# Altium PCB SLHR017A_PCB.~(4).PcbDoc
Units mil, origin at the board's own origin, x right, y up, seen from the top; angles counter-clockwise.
Board outline 3125 x 2100 mil, 2 copper layers (Top Layer, Bottom Layer), stack 61.2 mil thick; 61 components, 25 nets, 102 pads, 30 vias.
Unrouted connection lines stored in the file: 57.
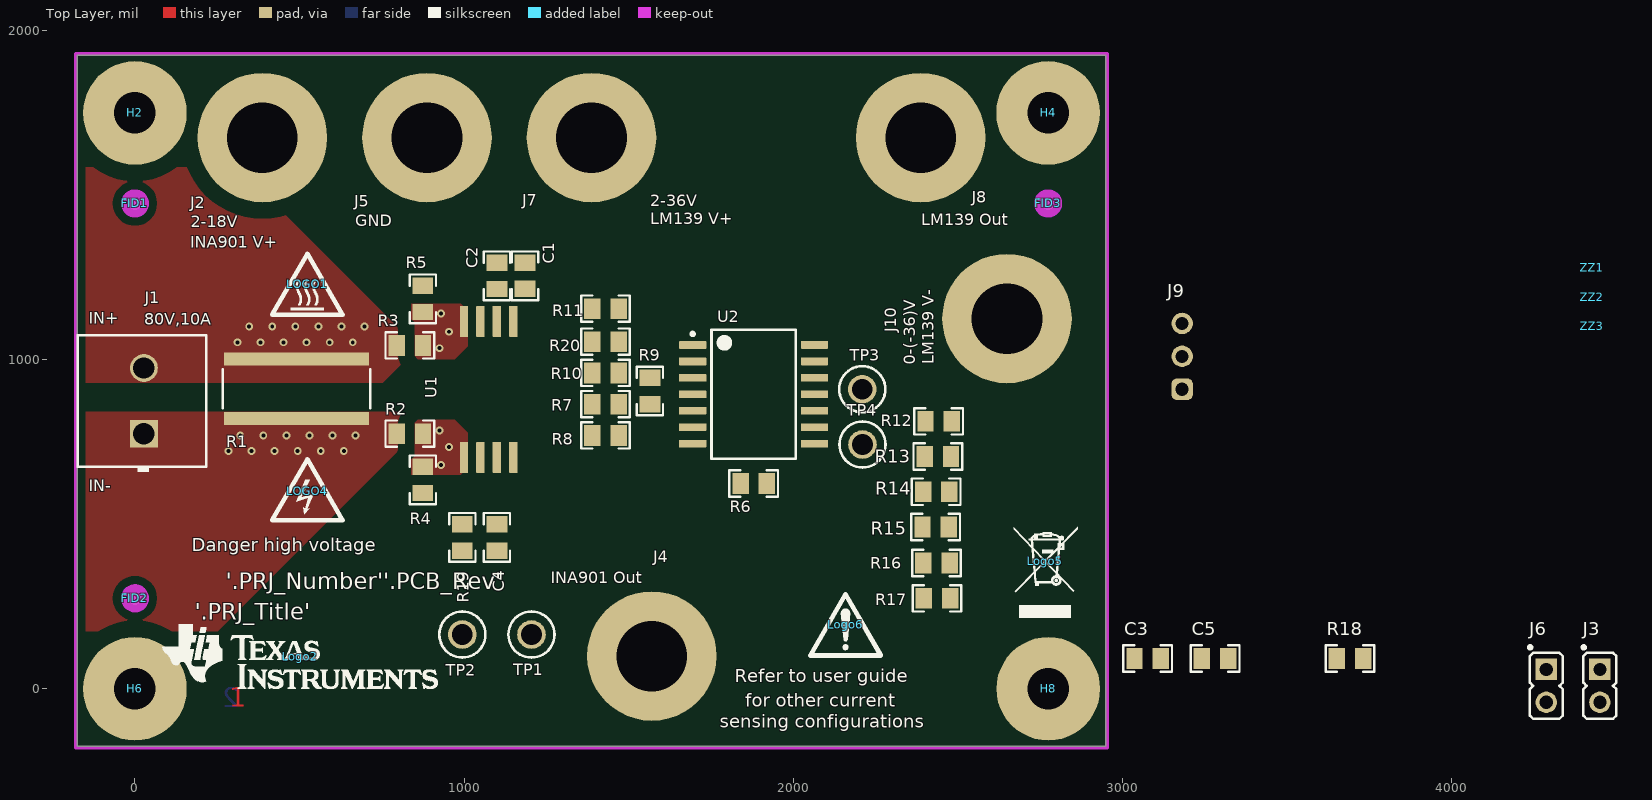
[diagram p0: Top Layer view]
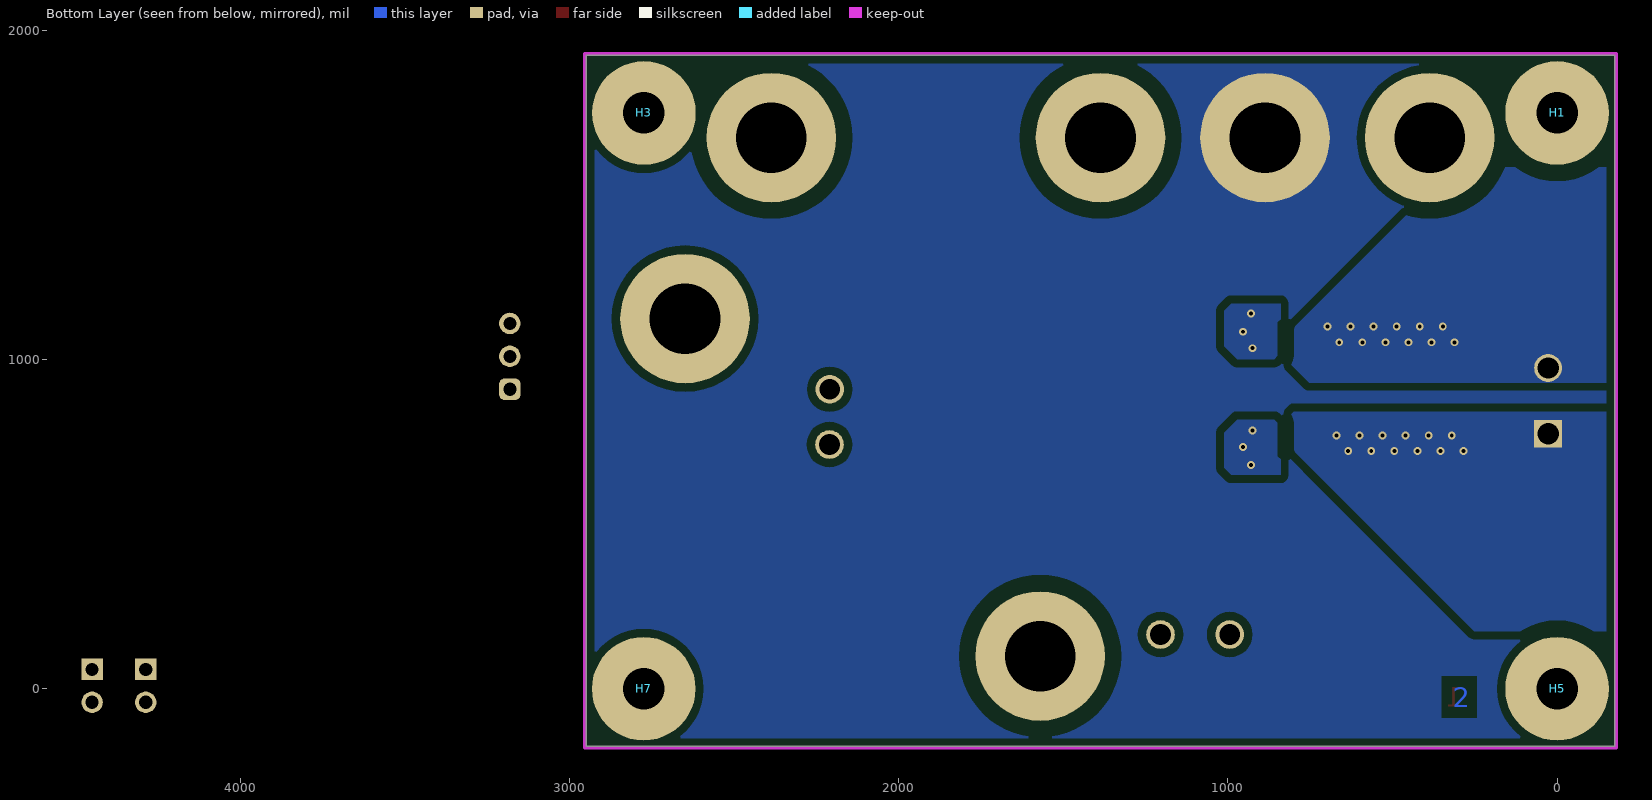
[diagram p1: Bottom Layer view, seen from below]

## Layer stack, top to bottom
Top Solder: solder mask 0.4, Solder Resist, Dk 3.5
Top Layer: signal copper 2.1
Dielectric1: core 57, FR-4 High Tg, Dk 4.8
Bottom Layer: signal copper 2.1
Bottom Solder: solder mask 0.4, Solder Resist, Dk 3.5

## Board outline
-175,-175 2950,-175 2950,1925 -175,1925
cut-out: -1791.23,-2214.56 -1781.23,-2214.56 -1781.23,-2204.56 -1791.23,-2204.56

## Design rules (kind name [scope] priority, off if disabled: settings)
AcuteAngle [All] p1: minimum=4.50000000000000E+0001 checktracksonly=FALSE
AssemblyTestPointUsage [All] p1: valid=2
Clearance Clearance_HV [InNetClass('HV_Net')] p1: gap=25 ignorepadtopadclearanceinfootprint=TRUE except(50: THPad-Poly Poly-Poly)
Clearance Clearance_Keepouts [((IsTrack Or IsArc) And Not InPoly) And IsFree and IsKeepOut vs ((IsTrack Or IsArc) And Not InPoly) And IsFree and IsKeepOut] p2: gap=0 ignorepadtopadclearanceinfootprint=FALSE
Clearance Clearance_Fiducial [InComponentClass('FiducialMark')] p3: gap=0 ignorepadtopadclearanceinfootprint=FALSE
Clearance Clearance_BoardEdge_MountingHoles [OnCopper and InComponentClass('Mounting Holes') vs IsKeepOut] p4: gap=40 ignorepadtopadclearanceinfootprint=FALSE except(15: Track-THPad)
Clearance Clearance_BoardEdge_Poly [OnCopper and InPoly vs IsKeepOut] p5: gap=25 ignorepadtopadclearanceinfootprint=FALSE
Clearance Clearance_Jack_Poly [InPolygon vs InPadClass('Jack')] p6: gap=25 ignorepadtopadclearanceinfootprint=FALSE except(50: Arc-Poly Track-Poly SMDPad-Poly THPad-Poly Via-Poly Fill-Poly Poly-Poly)
Clearance Clearance_Poly [InPolygon] p7: gap=25 ignorepadtopadclearanceinfootprint=FALSE
Clearance [All] p8: gap=15 ignorepadtopadclearanceinfootprint=FALSE
ComponentClearance ComponentClearance_MountingHoles_FiducialMarks [InComponentClass('Mounting Holes') vs InComponentClass('FiducialMark')] p1: gap=50 collisioncheckmode=3 verticalgap=10 showdistances=FALSE
ComponentClearance ComponentClearance_Logo [InComponentClass('Logo')] p2: gap=50 collisioncheckmode=3 verticalgap=100000 showdistances=FALSE
ComponentClearance ComponentClearance_ScrewToNut [(HasFootprint('NY PMS 440 0025 PH')) vs (HasFootprint('Keystone_1902C'))] p3: gap=0 collisioncheckmode=3 verticalgap=0 showdistances=FALSE
ComponentClearance ComponentClearance_MountingHoles [InComponentClass('Mounting Holes')] p4: gap=30 collisioncheckmode=3 verticalgap=100000 showdistances=FALSE
ComponentClearance [All] p5: gap=20 collisioncheckmode=3 verticalgap=10 showdistances=FALSE
DiffPairsRouting [All] p1: maxlimit=100 minlimit=10 mostfreqgap=10 toplayer_minwidth=15 toplayer_maxwidth=15 toplayer_prefwidth=15 bottomlayer_minwidth=15 bottomlayer_maxwidth=15 bottomlayer_prefwidth=15 maxuncoupledlength=1000
FabricationTestPointUsage TestPointUsage [All] p1: valid=2 allowmultiple=FALSE
FabricationTestpoint Testpoint [All] p1: side=3 testpointundercomponent=TRUE minsize=40 maxsize=100 preferedsize=60 minholesize=0 maxholesize=40 preferedholesize=32 testpointgrid=1 allowsidetop=TRUE allowsidebottom=TRUE usegrid=TRUE gridtolerance=0.01
FanoutControl Fanout_LCC [IsLCC] p1: bgadir=Out bgaviamode=Centered fanoutstyle=Auto fanoutdirection=Alternating viagrid=1 // Fanout_LCC (Default Rule)
FanoutControl Fanout_BGA [IsBGA] p2: bgadir=Out bgaviamode=Centered fanoutstyle=Auto fanoutdirection=Alternating viagrid=1 // Fanout_BGA (Default Rule)
FanoutControl Fanout_Default [All] p4: bgadir=Out bgaviamode=Centered fanoutstyle=Auto fanoutdirection=Alternating viagrid=1 // Fanout_Default (Default Rule)
FanoutControl Fanout_Small [(CompPinCount < 5)] p5: bgadir=Out bgaviamode=Centered fanoutstyle=Auto fanoutdirection=OutThenIn viagrid=1 // Fanout_Small (Default Rule)
HoleSize [All] p1: absolutevalues=TRUE maxlimit=251 minlimit=8 maxpercent=80.000 minpercent=20.000
MinimumAnnularRing [All] p1: minimumring=6
MinimumSolderMaskSliver MinimumSolderMaskSliver_Logo [InComponentClass('Logo') vs InComponentClass('Logo')] p1: minsoldermaskwidth=0.7
MinimumSolderMaskSliver [All] p2: minsoldermaskwidth=4
PlaneConnect [All] p1: planeconnectstyle=Relief reliefexpansion=10 reliefentries=4 reliefconductorwidth=10 reliefairgap=10
PolygonConnect [All] p1: connectstyle=Direct reliefconductorwidth=30 reliefentries=4 polygonreliefangle="90 Angle" airgapwidth=15
RoutingVias [All] p1: holewidth=12 width=24 viastyle="Through Hole" minholewidth=12 minwidth=24 maxholewidth=12 maxwidth=24
SilkToBoardRegionClearance [Not ((IsComment or IsDesignator) And (Hide <> 'False')) and not InRegion(1000,500,4000,800)] p1:
SilkToSilkClearance SilkToSilkClearance_Pb-FreeLogo [(HasFootprint('Pb-Free_Overlay_Medium') OR HasFootprint('Pb-Free_Overlay_Small')) vs (HasFootprint('Pb-Free_Overlay_Medium') OR HasFootprint('Pb-Free_Overlay_Small'))] p1: silktosilkclearance=0
SilkToSilkClearance [All] p2: silktosilkclearance=4
SilkToSolderMaskClearance SilkToComonentPadClearance [IsPad and InAnycomponent] p1: minsilkscreentomaskgap=5 clearancetoexposedcopper=TRUE
SilkToSolderMaskClearance "Silk to Solder Mask Opening" [All] p2: minsilkscreentomaskgap=4 clearancetoexposedcopper=FALSE
SolderMaskExpansion [All] p1: expansion=0
Width [All] p1: maxlimit=100 minlimit=6 preferedwidth=10 checkconnectedcopper=TRUE
15 further rules are at their usual default settings.

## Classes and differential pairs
component class Header: J3 J6 J9
component class SLHR017A_MainSheet: C1 C2 C3 C4 C5 J1 J2 J3 J4 J5 J6 J7 J8 J9 J10 R1 R2 R3 R4 R5 R6 R7 R8 R9 R10 R11 R12 R13 R14 R15 R16 R17 R18 R19 R20 TP1 TP2 TP3 TP4 U1 U2 U4
component class AssemblyNote: ZZ1 ZZ2 ZZ3
component class FiducialMark: FID1 FID2 FID3
component class SLHR017A_Hardware: FID1 FID2 FID3 H1 H2 H3 H4 H5 H6 H7 H8 LOGO1 Logo2 Logo3 LOGO4 Logo5 Logo6 Logo7 ZZ1 ZZ2 ZZ3
component class Logo: Logo2
component class "Mounting Holes": H2 H4 H6 H8
pad class Jack: J3-1 J4-1 J6-1 J7-1 J8-1

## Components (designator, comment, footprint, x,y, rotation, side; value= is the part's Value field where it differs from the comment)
C1 "C0805C104K1RACTU" 0805_HV 1185.18,1255.18 r90 top value=0.1uF
C2 "C0805C103F1GACTU" 0805_HV 1100,1255 r90 top value=0.01uF
C3 "C0805C101J1RACTU" 0805_HV 3077.5,92 r0 top value=100pF
C4 "C0805C103F1GACTU" 0805_HV 1100,460 r270 top value=0.01uF
C5 "C0805C103F1GACTU" 0805_HV 3282.5,92 r0 top value=0.01uF
FID1 "Fiducial" Fiducial10-20 0,1475 r270 top locked
FID2 "Fiducial" Fiducial10-20 0,275 r0 top locked
FID3 "Fiducial" Fiducial10-20 2775,1475 r180 top locked
H1 "1902C" Keystone_1902C 0,1750 r180 bottom locked
H2 "NY PMS 440 0025 PH" "NY PMS 440 0025 PH" 0,1750 r0 top locked
H3 "1902C" Keystone_1902C 2775,1750 r180 bottom locked
H4 "NY PMS 440 0025 PH" "NY PMS 440 0025 PH" 2775,1750 r0 top locked
H5 "1902C" Keystone_1902C 0,0 r180 bottom locked
H6 "NY PMS 440 0025 PH" "NY PMS 440 0025 PH" 0,0 r0 top locked
H7 "1902C" Keystone_1902C 2775.53,0 r180 bottom locked
H8 "NY PMS 440 0025 PH" "NY PMS 440 0025 PH" 2775.53,0 r0 top locked
J1 "039544-3002" Molex_039544-3002 27.17,875 r90 top
J2 "V+" Keystone_575-4 387.5,1675 r0 top
J3 "PBC02SAAN" Sullins_PBC02SAAN 4451.62,9 r0 top
J4 "INA_OUT" Keystone_575-4 1570.77,99.44 r0 top
J5 "GND" Keystone_575-4 887.5,1675 r0 top
J6 "PBC02SAAN" Sullins_PBC02SAAN 4288.84,9 r0 top
J7 "VPULLUP" Keystone_575-4 1387.5,1675 r0 top
J8 "COMP_OUT" Keystone_575-4 2387.5,1675 r0 top
J9 "TSW-103-07-G-S" TSW-103-07-G-S 3182.31,1010.33 r90 top
J10 "V-" Keystone_575-4 2650,1125 r0 top
LOGO1 "CAUTION HOT SURFACE" IEC_HotSurface_Small 524,1229.94 r0 top
Logo2 "Texas Instruments" TI_Stacked_Overlay_Small 502.13,97.86 r0 top
Logo3 "FCC disclaimer" FCC_disclaimer 1947.51,-1477.18 r270 top locked
LOGO4 "DANGER HIGH VOLTAGE" IEC_HighVoltage_Small 524,599.72 r0 top
Logo5 "WEEE logo" WEEE_Minimum 2765.79,387.53 r0 top
Logo6 "CAUTION.  READ USER GUIDE BEFORE USE" IEC_Caution_Small 2159.38,194.38 r0 top
R1 "KRL11050-C-R050-F-T1" 4320 490.99,911.59 r90 top locked value=0.05
R2 "ERJ-6GEY0R00V" 0805_HV 835.36,775.33 r0 top value=0
R3 "ERJ-6GEY0R00V" 0805_HV 835.36,1043.51 r0 top value=0
R4 "ERJ-6GEY0R00V" 0805_HV 875,635 r90 top value=0
R5 "ERJ-6GEY0R00V" 0805_HV 875,1185 r270 top value=0
R6 "ERJ-6GEY0R00V" 0805_HV 1880.36,623.81 r180 top value=0
R7 "ERJ-6GEY0R00V" 0805_HV 1430,865 r0 top value=0
R8 "ERJ-6GEY0R00V" 0805_HV 1430,770 r0 top locked value=0
R9 "ERJ-6GEYJ153V" 0805_HV 1565,905 r90 top locked value=15k
R10 "ERJ-6GEYJ153V" 0805_HV 1430,960 r0 top value=15k
R11 "ERJ-6GEYJ302V" 0805_HV 1430,1155 r180 top value=3.0k
R12 "RNCP0805FTD10K0" 0805_HV 2442.37,812.84 r180 top value=10.0k
R13 "CRCW080510M0FKEA" 0805_HV 2439.87,705.83 r0 top value=10.0Meg
R14 "RNCP0805FTD10K0" 0805_HV 2434.95,598.82 r0 top value=10.0k
R15 "CRCW080510M0FKEA" 0805_HV 2433.32,491.52 r0 top value=10.0Meg
R16 "RNCP0805FTD10K0" 0805_HV 2435.86,382.18 r0 top value=10.0k
R17 "CRCW080510M0FKEA" 0805_HV 2437.24,274.88 r0 top value=10.0Meg
R18 "RNCP0805FTD10K0" 0805_HV 3692.5,92 r0 top value=10.0k
R19 "RNCP0805FTD10K0" 0805_HV 994.96,460 r90 top value=10.0k
R20 "RNCP0805FTD10K0" 0805_HV 1430,1055 r180 top value=10.0k
TP1 "5010" Keystone5010 1204.96,164.96 r90 top
TP2 "5010" Keystone5010 994.96,164.96 r90 top
TP3 "5010" Keystone5010 2210.23,910.38 r90 top
TP4 "5010" Keystone5010 2210.94,742.37 r90 top
U1 "INA901HKX/EM" HKX0008A_Custom_B 1075,910 r90 top
U2 "LM139AWGRLQMLV" NAC0014A_N 1880,895 r0 top
ZZ1 "These assemblies are ESD sensitive, ESD precautions shall be observed." AssemblyNote 4427.97,1278.79 r0 top
ZZ2 "These assemblies must be clean and free from flux and all contaminants. Use of no clean flux is not acceptable." AssemblyNote 4427.97,1190.24 r0 top
ZZ3 "These assemblies must comply with workmanship standards IPC-A-610 Class 2, unless otherwise specified." AssemblyNote 4427.97,1101.68 r0 top

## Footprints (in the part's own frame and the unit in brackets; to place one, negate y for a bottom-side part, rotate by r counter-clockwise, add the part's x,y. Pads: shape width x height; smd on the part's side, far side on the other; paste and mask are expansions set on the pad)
0805_HV [mil] "0805 with 30mil clearance between pads"
  rect 50x63 smd: 1(-40,0) 2(40,0)
  silkscreen extent -74,-40 74,40, body extent -43,-29 43,29, height 57
4320 [mm] "SUSUMU"
  rect 1x11.2 smd: 1(-2.3,0) 2(2.3,0)
  silkscreen extent -1.5,-5.7 1.5,5.7, body extent -2.6,-5.6 2.6,5.6, height 0.7
AssemblyNote [mil] "Assembly Note"
FCC_disclaimer [mil]
Fiducial10-20 [mm]
  round 1 smd mask+0.5: 1(0,0)
  Top Layer keep-out circle w1.178: c0,0 r0.5
HKX0008A_Custom_B [mm] "CFP, 8-Leads, Body 6.73x6.74mm (max), Pitch 1.27mm, IPC Medium Density"
  rrect15% 2.4x0.65 smd: 1(-5.25,1.905) 2(-5.25,0.635) 3(-5.25,-0.635) 4(-5.25,-1.905) 5(5.25,-1.905) 6(5.25,-0.635) 7(5.25,0.635) 8(5.25,1.905)
  body extent -3.25,-3.24 3.25,3.24, height 2.51
IEC_Caution_Small [mil]
  silkscreen extent -107,-93 107,92
IEC_HighVoltage_Small [mil]
  silkscreen extent -107,-88 107,97
IEC_HotSurface_Small [mil]
  silkscreen extent -107,-93 107,92
Keystone5010 [mil] "Keystone Multipurpose loops"
  round 87 hole 63: 1(0,0)
  silkscreen extent -70,-70 70,70, body extent -63,-63 63,62, height 319
Keystone_575-4 [mm] "Banana Jack"
  round 10 hole 5.45: 1(0,0)
  body extent -3.95,-3.95 3.92,3.93, height 2.36
Keystone_1902C [mil] "Hex Standoff, 4-40 threaded, nylon"
  round 1 on Mech4: 0(0,0)
  body extent -145,-126 146,126, height 501
Molex_039544-3002 [mm] "Terminal Block, 5.08mm, 2x1, TH"
  rect 2.15x2.15 hole 1.65: 1(-2.54,0)
  round 2.15 hole 1.65: 2(2.54,0)
  silkscreen extent -5.5,-4.8 5.08,5.11, body extent -5.08,-4.8 5.08,5.11, height 14.48
NAC0014A_N [mm] "CFP-14"
  rrect17% 2.1x0.6 smd: 1(-4.7,3.81) 2(-4.7,2.54) 3(-4.7,1.27) 4(-4.7,0) 5(-4.7,-1.27) 6(-4.7,-2.54) 7(-4.7,-3.81) 8(4.7,-3.81) 9(4.7,-2.54) 10(4.7,-1.27) 11(4.7,0) 12(4.7,1.27) 13(4.7,2.54) 14(4.7,3.81)
  silkscreen extent -4.82,-4.97 3.25,4.97, body extent -5.21,-4.95 5.21,4.95, height 1.99
"NY PMS 440 0025 PH" [mm] "4-40 nylon screw and mounting hole"
  round 8 hole 3.2: 1(0,0)
  body extent -3.3,-3.3 3.3,3.3, height 2.69
Sullins_PBC02SAAN [mm] "Sullins 100mil, 1x2, 230 mil above insulator"
  rect 1.65x1.65 hole 1.016: 1(0,1.27)
  round 1.65 hole 1.016: 2(0,-1.27)
  silkscreen extent -1.37,-2.54 1.27,3.1, body extent -1.27,-2.54 1.27,2.54, height 8.38
TI_Stacked_Overlay_Small [mil]
  silkscreen extent -418,-98 418,98
TSW-103-07-G-S [mm] "Samtec 100mil, 1x3, 230 mil above insulator"
  rrect50% 1.65x1.65 hole 1.016: 1(-2.54,0)
  round 1.65 hole 1.016: 2(0,0) 3(2.54,0)
  body extent -3.81,-1.27 3.81,1.27, height 8.38
WEEE_Minimum [mil] "WEEElie bin"
  silkscreen extent -95,-172 99,104

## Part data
C1: library part CMP-0007722-2, "CAP, CERM, 0.1 uF, 100 V, +/- 10%, X7R, 0805", Cap_Case=0805, Manufacturer=Kemet, Supplier Part Number 1=399-3486-1-ND, TempCo=X7R, Tolerance_%=10%, Value1="0.064 ohm", Value2=100V, ValueDisplayed=0.1uF
C2 C4 C5: library part CMP-0007716-2, "CAP, CERM, 0.01 uF, 100 V, +/- 1%, C0G/NP0, 0805", Cap_Case=0805, Manufacturer=Kemet, Supplier Part Number 1=399-11160-1-ND, TempCo=C0G/NP0, Tolerance_%=1%, Value1=Unknown, Value2=100V, ValueDisplayed=0.01uF
C3: library part CMP-0007706-2, "CAP, CERM, 100 pF, 100 V, +/- 5%, X7R, 0805", Cap_Case=0805, Manufacturer=Kemet, Supplier Part Number 1=80-C0805C101J1R, TempCo=X7R, Tolerance_%=5%, Value1=Unknown, Value2=100V, ValueDisplayed=100pF
FID1 FID2 FID3: library part CMP-0077181-1, "Fiducial mark.  There is nothing to buy or mount.", Manufacturer=N/A
H1 H3 H5 H7: library part CMP-0003610-1, "Standoff, Hex, 0.5\"L #4-40 Nylon", Manufacturer=Keystone, Supplier Part Number 1=36-1902C-ND
H2 H4 H6 H8: library part CMP-0003617-1, "Machine Screw, Round, #4-40 x 1/4, Nylon, Philips panhead", Manufacturer="B&F Fastener Supply", Supplier Part Number 1=H542-ND
J1: library part CMP-0055345-1, "Terminal Block, 5.08mm, 2x1, TH", Color=Black, Current_A=15A, Manufacturer=Molex, Supplier Part Number 1=WM7853-ND, Voltage_V=300V
J2 J4 J5 J7 J8 J10: library part CMP-0055165-2, "Standard Banana Jack, Uninsulated, 5.5mm", Manufacturer=Keystone, PartNumber=575-4, Supplier Part Number 1=36-575-4-ND
J3 J6: library part CMP-0054566-1, "Header, 100mil, 2x1, Gold, TH", Color=Black, Current_A=3A, Manufacturer="Sullins Connector Solutions", Supplier Part Number 1=S1011E-02-ND, Voltage_V=1.8kV
J9: library part CMP-0075407-2, "Header, 100mil, 3x1, Gold, TH", Color=Black, Current_A=6.3A, Manufacturer=Samtec, Supplier Part Number 1=SAM1029-03-ND, Voltage_V=550V
LOGO1: library part CMP-0074837-1, "IEC 61010-1 Hot Surface Warning"
Logo2: library part CMP-0074838-1, "Texas Instrument Corporate Signature"
Logo3: library part CMP-0074847-1, "FCC_disclaimer"
LOGO4: library part CMP-0074835-1, "IEC 61010-1 High Voltage Warning"
Logo5: library part CMP-0074769-1
Logo6: library part CMP-0074836-1, "IEC 61010-1 Caution Warning"
R1: library part CMP-0015099-2, "RES, 0.05, 1%, 6 W, 4320_WIDE", Manufacturer="Susumu Co Ltd", Power_W=6W, Supplier Part Number 1=KRL11C.050CT-ND, TempCo="50 ppm/C", Tolerance_%=1%, Value_Code=R050, ValueDisplayed=0.05
R2 R3 R4 R5 R6 R7 R8: library part CMP-0020616-3, "RES, 0, 5%, 0.125 W, AEC-Q200 Grade 0, 0805", Manufacturer=Panasonic, Power_W=125mW, Supplier Part Number 1=P0.0ACT-ND, TempCo="600 ppm/C", Tolerance_%=5%, Value2=0.125W, Value_Code=0000, ValueDisplayed=0
R9 R10: library part CMP-0020646-3, "RES, 15 k, 5%, 0.125 W, AEC-Q200 Grade 0, 0805", Manufacturer=Panasonic, Power_W=125mW, Supplier Part Number 1=P15KACT-ND, TempCo="200 ppm/C", Tolerance_%=5%, Value2=0.125W, Value_Code=15k0, ValueDisplayed=15k
R11: library part CMP-0020698-3, "RES, 3.0 k, 5%, 0.125 W, AEC-Q200 Grade 0, 0805", Manufacturer=Panasonic, Power_W=125mW, Supplier Part Number 1=P3.0KACT-ND, TempCo="200 ppm/C", Tolerance_%=5%, Value2=0.125W, Value_Code=3k00, ValueDisplayed=3.0k
R12 R14 R16 R18 R19 R20: library part CMP-0084247-1, "RES, 10.0 k, 1%, 0.25 W, AEC-Q200 Grade 0, 0805", Manufacturer="Stackpole Electronics Inc", Power_W=250mW, TempCo="100 ppm/C", Tolerance_%=1%, Value2=0.25W, Value_Code=10k0, ValueDisplayed=10.0k
R13 R15 R17: library part CMP-0020846-3, "RES, 10.0 M, 1%, 0.125 W, AEC-Q200 Grade 0, 0805", Manufacturer=Vishay-Dale, Power_W=125mW, Supplier Part Number 1=541-10.0MCCT-ND, TempCo="100 ppm/C", Tolerance_%=1%, Value2=0.125W, Value_Code=10M0, ValueDisplayed=10.0M
TP1 TP2 TP3 TP4: library part CMP-0055147-1, "Test Point, Multipurpose, Red, TH", Color=Red, Manufacturer=Keystone, Supplier Part Number 1=36-5010-ND
U1: library part CMP-0081563-2, "Voltage Output, Unidirectional Measurement Current-Shunt Monitor, HKX0008A (CFP-8)", Alternate Manufacturer="Texas Instruments", Rating=Space
U2: library part CMP-0068426-2, "Low Power Low Offset Voltage Quad Comparator, NAC0014A (CFP-14)", Manufacturer="Texas Instruments", Operating Temperature Range="-55 to 125 C", Rating=Space
ZZ1: library part CMP-0077236-1
ZZ2: library part CMP-0077237-1
ZZ3: library part CMP-0077238-1

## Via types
v1: diameter 24, hole 12, Top Layer to Bottom Layer, tented both sides, 30 vias

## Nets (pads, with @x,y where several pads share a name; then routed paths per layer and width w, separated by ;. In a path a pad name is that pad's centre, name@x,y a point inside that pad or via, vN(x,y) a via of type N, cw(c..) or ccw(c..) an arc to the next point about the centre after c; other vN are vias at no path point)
GND: C1.2 C2.2 C4.2 J5.1 J9.1 R4.1 R5.1 R10.1 R12.1 R13.1 R14.1 R15.1 R16.1 R17.1 R18.2 R19.2 R20.2 U1.2
NetC1_1: C1.1 C2.1 J2.1 J3.1 U1.6 U2.3
NetC3_1: C3.1 R3.2 R5.2 U1.8
  other v1: 925,1035 955,1085 930,1140
NetC3_2: C3.2 R2.2 R4.2 U1.1
  other v1: 930,680 955,735 925,785
NetC4_1: C4.1 R6.1 TP1.1 U1.4
NetC5_1: C5.1 R6.2 TP2.1 U1.3
NetC5_2: C5.2 J4.1 R7.1 R8.1 U1.5
NetJ1_1: J1.1 R1.1 R2.1
  other v1: 284.71,722.65 354.71,722.65 424.71,722.65 494.71,722.65 564.71,722.65 634.71,722.65 320.06,770.19 390.06,770.19 460.06,770.19 530.06,770.19 600.06,770.19 670.06,770.19
NetJ1_2: J1.2 R1.2 R3.1
  other v1: 311.93,1052.99 381.93,1052.99 451.93,1052.99 521.93,1052.99 591.93,1052.99 661.93,1052.99 347.28,1100.53 417.28,1100.53 487.28,1100.53 557.28,1100.53 627.28,1100.53 697.28,1100.53
NetJ3_2: J3.2 J6.1 R9.2
NetJ6_2: J6.2 J7.1 R11.2
NetJ8_1: J8.1 R11.1 U2.2
NetJ9_2: J9.2 U2.12
NetJ9_3: J9.3 J10.1
NetR7_2: R7.2 R9.1 R10.2 TP3.1 U2.4
NetR8_2: R8.2 TP4.1 U2.5
NetR12_2: R12.2 U2.8
NetR13_2: R13.2 U2.9
NetR14_2: R14.2 U2.6
NetR15_2: R15.2 U2.7
NetR16_2: R16.2 U2.10
NetR17_2: R17.2 U2.11
NetR18_1: R18.1 U2.1
NetR19_1: R19.1 U2.13
NetR20_1: R20.1 U2.14
pads on no net: FID1.1 FID2.1 FID3.1 H1.0 H2.1 H3.0 H4.1 H5.0 H6.1 H7.0 H8.1 U1.7

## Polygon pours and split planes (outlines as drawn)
NetC3_2 on Top Layer "GND" (solid, remove dead copper, pour order 264): 840.29,649.85 840.29,696.87 849.75,706.32 849.75,808.11 859.85,818.22 972.21,818.22 1011.88,778.55 1011.88,671.56 990.17,649.85
NetC3_1 on Top Layer "GND" (solid, remove dead copper, pour order 265): 840.29,1170.15 840.29,1122.86 849.75,1113.4 849.75,1011.89 859.85,1001.78 972.21,1001.78 1011.88,1041.45 1011.88,1148.44 990.17,1170.15
NetJ1_1 on Top Layer "GND" (solid, remove dead copper, pour order 266): -174.94,842.31 799.54,842.31 820.22,821.63 820.22,743.75 717.82,641.35 251.68,175.21 -172.82,175.21
NetJ1_2 on Top Layer "GND" (solid, remove dead copper, pour order 267): -175.09,930.77 752.62,930.77 820.22,998.37 820.22,1076.25 717.82,1178.65 310.93,1585.54 -173.01,1585.54
GND on Bottom Layer "GND" (solid, remove dead copper, pour order 272): -174.92,-174.96 2949.91,-174.96 2949.92,-174.96 2949.92,1925.05 2949.89,1925.07 -174.89,1925.07 -175,1924.96
NetC3_1 on Bottom Layer "GND" (solid, remove dead copper, pour order 269): 840.29,1170.15 840.29,1122.86 849.75,1113.4 849.75,1011.89 859.85,1001.78 972.21,1001.78 1011.88,1041.45 1011.88,1148.44 990.17,1170.15
NetC3_2 on Bottom Layer "GND" (solid, remove dead copper, pour order 268): 840.29,649.85 840.29,696.87 849.75,706.32 849.75,808.11 859.85,818.22 972.21,818.22 1011.88,778.55 1011.88,671.56 990.17,649.85
NetJ1_1 on Bottom Layer "GND" (solid, remove dead copper, pour order 270): -174.94,842.31 799.54,842.31 820.22,821.63 820.22,743.75 717.82,641.35 251.68,175.21 -172.82,175.21
NetJ1_2 on Bottom Layer "GND" (solid, remove dead copper, pour order 271): -175.09,930.77 752.62,930.77 820.22,998.37 820.22,1076.25 717.82,1178.65 310.93,1585.54 -173.01,1585.54

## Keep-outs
Keep-Out Layer:
  lines w10: -180,-180 2955,-180 2955,1930 -180,1930 -180,-180
  text ".Layer_Name" at -522.23,-1539.06 h60

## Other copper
Top Layer:
  text "1" at 287.08,-55.09 h60
  text ".Layer_Name" at -522.23,-1539.06 h60
Bottom Layer:
  text "2" at 316.97,-55.48 h60
  text ".Layer_Name" at -522.23,-1539.06 h60

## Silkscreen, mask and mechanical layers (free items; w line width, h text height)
Top Overlay:
  text "2-36V" at 1566.56,1466.79 h35
  text "LM139 V+" at 1566.01,1412.12 h35
  text "LM139 Out" at 2390.02,1409.42 h35
  text "GND" at 669.35,1405.39 h35
  text "2-18V" at 169.23,1402.02 h35
  text "INA901 V+" at 168.19,1339.58 h35
  text "IN+" at -139.72,1109.97 h35
  text "80V,10A" at 28.26,1106.78 h35
  text "LM139 V-" at 2427.31,986.4 h35 r90
  text "0-(-36)V" at 2371.89,984.24 h35 r90
  text "IN-" at -139.72,599.99 h35
  text "Danger high voltage" at 172.24,418.2 h40
  text "INA901 Out" at 1263.83,321.35 h35
  text "'.PRJ_Number''.PCB_Rev'" at 276.6,302.79 h50
  text "'.PRJ_Title'" at 182.3,210.53 h50
  text "Refer to user guide" at 1822.52,19.52 h40
  text "for other current" at 1854.54,-54.96 h40
  text "sensing configurations" at 1776.8,-118.4 h40
  text ".Layer_Name" at -522.23,-1539.06 h60
Bottom Overlay:
  text ".Layer_Name" at -522.23,-1539.06 h60
Top Paste:
  text ".Layer_Name" at -522.23,-1539.06 h60
Bottom Paste:
  text ".Layer_Name" at -522.23,-1539.06 h60
Top Solder:
  text ".Layer_Name" at -522.23,-1539.06 h60
  text ".Layer_Name" at -522.23,-1539.06 h60
Bottom Solder:
  text ".Layer_Name" at -522.23,-1539.06 h60
Drill Guide:
  text ".Layer_Name" at -522.23,-1539.06 h60
M1 Board Outline:
  the board outline again, w10
  text ".Layer_Name" at -522.23,-1539.06 h60
M2 Board Dimensions:
  rectangle: -974.23,-1080.56 -599.23,-955.56
  rectangle: -1099.23,-955.56 -974.23,-830.56
  lines w7: -1099.23,-955.56 -99.23,-955.56 ; -974.23,-1080.56 -974.23,-830.56 ; -849.23,-1080.56 -849.23,-830.56 ; -599.23,-1080.56 -599.23,-830.56 ; -349.23,-1080.56 -349.23,-830.56 ; -1099.23,-1080.56 -1099.23,-830.56 -99.23,-830.56 -99.23,-1080.56 -1099.23,-1080.56
  text ".Layer_Name" at -522.23,-1539.06 h60
M3 3D STEP Top:
  text ".Layer_Name" at -522.23,-1539.06 h60
M4 3D STEP Bottom:
  text ".Layer_Name" at -522.23,-1539.06 h60
M5 Assembly Top:
  lines w10: -1391.23,-1610.73 5208.77,-1610.73 ; -1391.23,-1407.4 5210.77,-1407.4 ; -1391.23,-1204.06 -1391.23,-1814.06 2613.77,-1814.06 5210.77,-1814.06 5210.77,-1204.06 -1390.73,-1204.06 -1390.73,-1814.06 184.77,-1814.06 ; 1073.77,-1814.06 1073.77,-1204.06 ; 2340.77,-1407.4 2340.77,-1204.06 ; 3180.77,-1407.4 3180.77,-1204.06 ; 3802.77,-1820.56 3802.77,-1617.73
  text "COMPONENTS MARKED 'DNP' SHOULD NOT BE POPULATED." at 54.27,-999.06 h60
  text "ASSEMBLY VARIANT:" at 53.77,-1114.56 h60
  text ".VariantName" at 1089.77,-1114.56 h60
  text "PCB VIEWED FROM TOP SIDE" at -1327.73,-1336.23 h60
  text "BOARD #:" at 1148.77,-1336.23 h60
  text ".PRJ_Number" at 1694.27,-1336.23 h60
  text "REV:" at 2538.77,-1336.23 h60
  text ".PCB_Rev" at 2830.27,-1336.23 h60
  text "SVN REV:" at 3376.77,-1336.23 h60
  text ".VersionControl_RevNumber" at 3882.77,-1336.23 h60
  text "TID #:" at 1148.77,-1539.56 h60
  text ".TID" at 1694.27,-1539.56 h60
  text "PLOT NAME =" at -1327.73,-1744.9 h60
  text ".plot_File_Name" at -522.23,-1744.9 h60
  text "GENERATED    :" at 1150.77,-1744.9 h60
  text ".Print_Date" at 2020.27,-1744.9 h60
  text ".Print_Time" at 2749.27,-1744.9 h60
  text "TEXAS INSTRUMENTS" at 4013.77,-1744.9 h60
M6 Assembly Bottom:
  lines w10: -1391.73,-1407.9 5210.27,-1407.9 ; -1389.73,-1611.23 5210.27,-1611.23 ; 16.27,-1821.06 16.27,-1618.23 ; 638.27,-1407.9 638.27,-1204.56 ; 1478.27,-1407.9 1478.27,-1204.56 ; 2745.27,-1814.56 2745.27,-1204.56 ; 3634.27,-1814.56 5209.77,-1814.56 5209.77,-1204.56 -1391.73,-1204.56 -1391.73,-1814.56 1205.27,-1814.56 5210.27,-1814.56 5210.27,-1204.56
  text "COMPONENTS MARKED 'DNP' SHOULD NOT BE POPULATED." at 5002.77,-998.56 h60
  text ".VariantName" at 3958.77,-1114.56 h60
  text "ASSEMBLY VARIANT:" at 4997.77,-1114.56 h60
  text ".VersionControl_RevNumber" at -63.73,-1336.73 h60
  text "SVN REV:" at 442.27,-1336.73 h60
  text ".PCB_Rev" at 988.77,-1336.73 h60
  text "REV:" at 1280.27,-1336.73 h60
  text ".PRJ_Number" at 2124.77,-1336.73 h60
  text "BOARD #:" at 2670.27,-1336.73 h60
  text "PCB VIEWED FROM BOTTOM SIDE" at 5146.77,-1336.73 h60
  text ".TID" at 2124.77,-1540.06 h60
  text "TID #:" at 2670.27,-1540.06 h60
  text "TEXAS INSTRUMENTS" at -194.73,-1745.4 h60
  text ".Print_Time" at 1069.77,-1745.4 h60
  text ".Print_Date" at 1798.77,-1745.4 h60
  text "GENERATED    :" at 2668.27,-1745.4 h60
  text ".plot_File_Name" at 4341.27,-1745.4 h60
  text "PLOT NAME =" at 5146.77,-1745.4 h60
M7 LPKF Text Top:
  text ".Layer_Name" at -522.23,-1539.06 h60
M8 LPKF Text Bottom:
  text ".Layer_Name" at -522.23,-1539.06 h60
M9 Title Sheet:
  drawing of 57 lines, arcs and shapes, not listed
  text "1" at -359.39,7355.94 h70
  text "2" at 2136.27,7355.94 h70
  text "3" at 4625.61,7355.94 h70
  text "4" at 7132.28,7355.94 h70
  text "5" at 9631.27,7355.94 h70
  text "6" at 12136.27,7355.94 h70
  text "A" at -1515.73,6212.94 h70
  text "A" at 13284.27,6212.94 h70
  text "B" at -1515.73,3832.94 h70
  text "B" at 13284.27,3832.94 h70
  text "C" at -1515.73,1457.94 h70
  text "C" at 13284.27,1457.94 h70
  text "PROJECT TITLE:" at 10244.27,-403.06 h45
  text ".PRJ_Title" at 10294.27,-536.39 h70
  text "DESIGNED FOR:" at 10244.27,-704.06 h45
  text ".PRJ_Customer" at 10294.27,-844.06 h70
  text "D" at -1515.73,-912.06 h70
  text "D" at 13284.27,-912.06 h70
  text "FILE NAME:" at 10244.27,-1004.06 h45
  text ".PCB_File_Name_No_Path" at 10294.27,-1124.06 h70
  text "Texas Instruments (TI) and/or its licensors do not warrant the accuracy or completeness of this specification" at 5274.77,-1285.9 h45
  text "ENGINEER:" at 10244.27,-1294.06 h45
  text "LAYOUT BY:" at 11749.27,-1294.06 h45
  text "or any information contained therein. TI and/or its licensors do not warrant that this design will meet" at 5229.79,-1398.57 h45
  text ".PRJ_Engineer" at 10294.27,-1449.05 h70
  text ".PCB_Layout" at 11799.77,-1449.05 h70
  text "the specifications, will be suitable for your application or fit for any particular purpose, or will operate in" at 5229.79,-1511.23 h45
  text ".Layer_Name" at -522.23,-1539.06 h60
  text "ALTIUM DESIGNER VERSION:" at 11749.27,-1604.06 h45
  text "an implementation. TI and/or its licensors do not warrant that the design is production worthy. You should" at 5229.79,-1623.9 h45
  text "completely validate and test your design implementation to confirm the system functionality for your application." at 5274.77,-1736.56 h45
  text ".print_Scale" at 10294.27,-1737.39 h70
  text ".Application_BuildNumber" at 11799.77,-1737.39 h70
  text "1" at -359.39,-1944.06 h70
  text "2" at 2136.27,-1944.06 h70
  text "3" at 4625.61,-1944.06 h70
  text "4" at 7132.28,-1944.06 h70
  text "5" at 9631.27,-1944.06 h70
  text "6" at 11488.98,-1949.87 h70
  text "WO#307451-7449-D" at 11888.89,-1952.37 h70
M10 Fab Notes:
  drawing of 189 lines, arcs and shapes, not listed
  text "DESIGN INFORMATION" at 11296.29,5675.61 h60
  text "20" at 11706.72,5544.28 h60
  text "MIN. TRACK WIDTH:" at 10651.73,5543.49 h60
  text "MIL" at 11902.73,5543.49 h60
  text "MIN. CLEARANCE:" at 10651.73,5419.36 h60
  text "MIL" at 11902.73,5419.36 h60
  text "19.7" at 11661.15,5416.95 h60
  text "24" at 11687.7,5303.69 h60
  text "MIN. VIA PAD SIZE:" at 10651.73,5295.23 h60
  text "MIL" at 11902.73,5295.23 h60
  text "0.05mm (2MIL)" at 11346.73,5165.33 h60
  text "MINIMUM ANNULAR RING" at 10322.5,5157.11 h60
  text "EXTERNAL" at 12054.73,5157.11 h60
  text "PER" at 10522.5,5046.99 h60
  text "IPC-D-275 CLASS 2 LEVEL C" at 10742.5,5046.98 h60
  text "MIL, HOLES" at 12230.73,4946.51 h60
  text "+/-" at 11838.27,4937.92 h60
  text "+/-" at 12692.27,4937.92 h60
  text "REGISTRATION TOLERANCES:" at 10322.5,4936.86 h60
  text "METAL" at 11522.27,4936.86 h60
  text "5" at 12098.47,4936.86 h60
  text "3" at 12931.47,4936.86 h60
  text "MIL" at 13047.73,4936.86 h60
  text "HOLE SIZE TOLERANCE (UNLESS OTHERWISE SPECIFIED):" at 10322.5,4838.54 h60
  text "+/-" at 12692.27,4835.67 h60
  text "3" at 12931.47,4834.61 h60
  text "MIL" at 13047.73,4834.6 h60
  text "MATERIAL:" at 10247.73,4696.96 h60
  text "FR-4 High Tg" at 11234.17,4568.43 h60
  text "FR-408" at 10668.73,4555.93 h60
  text "OTHER" at 12156.73,4555.93 h60
  text "X" at 11085.86,4554.44 h60
  text "62 MIL (1.6mm) +/-10%" at 10988.83,4412.9 h60
  text "X" at 10868.74,4410.44 h60
  text "THICKNESS:" at 10322.5,4404.68 h60
  text "OTHER" at 12273.73,4404.68 h60
  text "TOLERANCE:" at 10322.5,4266.36 h60
  text "X" at 11170.74,4266.36 h60
  text "ANSI IPC-6012 TYPE 3 CLASS 2" at 11348.75,4266.36 h60
  text "OTHER +/-" at 11348.73,4122.17 h60
  text "BOW & TWIST:" at 10322.5,3976.98 h60
  text "X" at 11170.74,3976.98 h60
  text "ANSI IPC-6012 TYPE 3 CLASS 2" at 11348.75,3976.98 h60
  text "OTHER +/-" at 11348.73,3830.29 h60
  text "DRILLING:" at 10247.73,3699.67 h60
  text "NC_DRILL FILES" at 12008.73,3594.48 h60
  text "REFERENCE:" at 10322.5,3590.54 h60
  text "X" at 10979.74,3590.44 h60
  text "AS SHOWN" at 11157.73,3590.54 h60
  text "X" at 11880.74,3590.54 h60
  text "OTHER" at 12306.73,3448.29 h60
  text "PTH COPPER THICKNESS:" at 10322.18,3444.76 h60
  text "X" at 11461.41,3444.76 h60
  text "20-30 um" at 11589.41,3444.76 h60
  text "BOARD FINISH:" at 10247.73,3297.16 h60
  text "SILKSCREEN:" at 10402.95,3187.04 h60
  text "X" at 11360.74,3187.04 h60
  text "TOP" at 11477.73,3187.04 h60
  text "BOTTOM" at 11988.73,3187.04 h60
  text "SILKSCREEN COLOR:" at 10402.95,3031.85 h60
  text "X" at 11359.74,3031.85 h60
  text "WHITE" at 11477.73,3031.85 h60
  text "OTHER" at 11988.73,3031.85 h60
  text "X" at 11487.3,2892.33 h60
  text "GREEN" at 11608.73,2888.4 h60
  text "OTHER" at 12226.73,2888.4 h60
  text "SOLDER RESIST COLOR:" at 10402.95,2881.53 h60
  text "X" at 11490.74,2734.15 h60
  text "MATTE" at 11608.73,2734.15 h60
  text "SEMI-GLOSS" at 12226.27,2733.51 h60
  text "IMMERSION GOLD (ENIG)" at 11308.73,2561.38 h60
  text "ENEPIG" at 12646.27,2554.16 h60
  text "SURFACE FINISH:" at 10247.73,2553.16 h60
  text "X" at 11130.74,2553.16 h60
  text "IMM. TIN/SILVER OR EQUIV" at 10577.27,2415.84 h60
  text "OTHER" at 12008.73,2411.9 h60
  text "ARRAY/PANEL:" at 10247.73,2256.53 h60
  text "CUT AND TRIM PER M1 BOARD OUTLINE" at 11308.73,2248.3 h60
  text "N.C. ROUTE" at 11308.73,2112.34 h60
  text "V. SCORE" at 12174.73,2112.34 h60
  text "X" at 11991.92,2110.76 h60
  text "CERTIFICATION:" at 10247.73,1983.21 h60
  text "MATERIALS AND WORKMANSHIP FOR ALL PCBS" at 10972.73,1983.21 h60
  text "TO MEET OR EXCEED THE REQUIREMENTS OF:" at 10972.73,1889.15 h60
  text "X" at 10610.24,1760.52 h60
  text "ANSI IPC-A-600F CLASS ->" at 10738.23,1760.52 h60
  text "X" at 12386.24,1760.52 h60
  text "2" at 12496.23,1760.52 h60
  text "1" at 12181.23,1759.02 h60
  text "3" at 12850.23,1759.02 h60
  text "X" at 11422.24,1612.83 h60
  text "RoHS" at 11550.23,1612.83 h60
  text "OTHER" at 12194.64,1612.83 h60
  text "PER ORDER" at 12591.69,1612.83 h60
  text "ALL BOARDS MUST MEET OR EXCEED UL94-V0 REQUIREMENTS." at 10275.27,1459.01 h60
  text "PCB MUST BEAR THE UL94V-0 UL REGISTERED MATERIAL ID NUMBER" at 10275.27,1342.94 h60
  text "ADDITIONAL REQUIREMENTS:" at 10247.73,1173.52 h60
  text "MICROSECTION:" at 10322.5,1066.39 h60
  text "YES" at 11228.23,1066.39 h60
  text "REQUIRED" at 12089.73,922.06 h60
  text "BARE BOARD ELEC. TEST:" at 10322.5,919.2 h60
  text "NONE" at 11628.23,919.2 h60
  text "X" at 11971.74,919.2 h60
  text "PER ORDER" at 12681.73,919.2 h60
  text "XX MIL VIAS REQUIRE NON-CONDUCTIVE FILL AND PLANARIZE" at 10490.65,714.26 h59
  text "XX MIL VIAS REQUIRE CONDUCTIVE FILL AND PLANARIZE" at 10498.65,610.28 h60
  text "FAB NOTES:" at 4273.61,546.93 h60
  text "OUTER XX MIL VIAS REQUIRE 50 OHM SINGLE-ENDED IMPEDANCE" at 10497.66,446.89 h58
  text "1. THE SOLDER MASK IMAGES THAT ARE THE SAME SIZE AS THE COMPONENT PADS MAY BE ENLARGED AS PER THE" at 4285.55,398.79 h60
  text "LAYER 2 & 3 (INNER LAYERS) XX MIL WIDE, XX MIL SPACE" at 10497.78,291.96 h60
  text "MANUFACTURING CAPABILITIES BUT NOT BEYOND 0.08MM PER SIDE OR 0.15MM OVERALL." at 4446.89,265.18 h60
  text "ALL OTHER SOLDER MASK IMAGES SHALL NOT BE MODIFIED." at 4446.89,131.58 h60
  text ".Layer_Name" at -522.23,-1539.06 h60
M11 Gerber Information:
  lines w10: -1391.23,-1610.73 5208.77,-1610.73 ; -1391.23,-1407.4 5210.77,-1407.4 ; -1391.23,-1204.06 -1391.23,-1814.06 2613.77,-1814.06 5210.77,-1814.06 5210.77,-1204.06 -1390.73,-1204.06 -1390.73,-1814.06 184.77,-1814.06 ; 1073.77,-1814.06 1073.77,-1204.06 ; 2340.77,-1407.4 2340.77,-1204.06 ; 3180.77,-1407.4 3180.77,-1204.06 ; 3802.77,-1820.56 3802.77,-1617.73
  text "ALL ARTWORK VIEWED FROM TOP SIDE" at -1327.73,-1336.23 h60
  text "BOARD #:" at 1148.77,-1336.23 h60
  text ".PRJ_Number" at 1694.27,-1336.23 h60
  text "REV:" at 2538.77,-1336.23 h60
  text ".PCB_Rev" at 2830.27,-1336.23 h60
  text "SVN REV:" at 3376.77,-1336.23 h60
  text ".VersionControl_RevNumber" at 3882.77,-1336.23 h60
  text "LAYER NAME =" at -1327.73,-1539.06 h60
  text "TID #:" at 1148.77,-1539.56 h60
  text ".TID" at 1694.27,-1539.56 h60
  text "PLOT NAME =" at -1327.73,-1744.9 h60
  text ".plot_File_Name" at -522.23,-1744.9 h60
  text "GENERATED    :" at 1150.77,-1744.9 h60
  text ".Print_Date" at 2020.27,-1744.9 h60
  text ".Print_Time" at 2749.27,-1744.9 h60
  text "TEXAS INSTRUMENTS" at 4013.77,-1744.9 h60
M12 Stackup:
  drawing of 292 lines, arcs and shapes, not listed
  text "STACKUP TABLE:" at 4158.14,4148.01 h80
  text "Layer" at 4224.56,3976.37 h60
  text "Name" at 4634.47,3976.37 h60
  text "Material" at 5494.24,3976.37 h60
  text "Thickness" at 6354.01,3976.37 h60
  text "Constant" at 7003.84,3976.37 h60
  text "Board Layer Stack" at 7573.7,3976.37 h60
  text "Board Layer Stack" at 8693.39,3976.37 h60
  text "1" at 4224.56,3856.37 h60
  text "Top Overlay" at 4634.47,3856.37 h60
  text "2" at 4224.56,3736.37 h60
  text "Top Solder" at 4634.47,3736.37 h60
  text "Solder Resist" at 5494.24,3736.37 h60
  text "0.40mil" at 6354.01,3736.37 h60
  text "3.5" at 7003.84,3736.37 h60
  text "3" at 4224.56,3616.37 h60
  text "Top Layer" at 4634.47,3616.37 h60
  text "Copper" at 5494.24,3616.37 h60
  text "2.10mil" at 6354.01,3616.37 h60
  text "4" at 4224.56,3496.37 h60
  text "Dielectric1" at 4634.47,3496.37 h60
  text "FR-4 High Tg" at 5494.24,3496.37 h60
  text "57.00mil" at 6354.01,3496.37 h60
  text "4.8" at 7003.84,3496.37 h60
  text "5" at 4224.56,3376.37 h60
  text "Bottom Layer" at 4634.47,3376.37 h60
  text "Copper" at 5494.24,3376.37 h60
  text "2.10mil" at 6354.01,3376.37 h60
  text "6" at 4224.56,3256.37 h60
  text "Bottom Solder" at 4634.47,3256.37 h60
  text "Solder Resist" at 5494.24,3256.37 h60
  text "0.40mil" at 6354.01,3256.37 h60
  text "3.5" at 7003.84,3256.37 h60
  text ".Layer_Name" at -522.23,-1539.06 h60
M13 Component Bodies Top:
  text ".Layer_Name" at -522.23,-1539.06 h60
M14 Component Bodies Bottom:
  text ".Layer_Name" at -522.23,-1539.06 h60
M15 Courtyards Top:
  text ".Layer_Name" at -522.23,-1539.06 h60
M16 Courtyards Bottom:
  text ".Layer_Name" at -522.23,-1539.06 h60
Drill Drawing:
  lines w10: 4224.19,2461.6 4290.86,2461.6 4290.86,2528.26 4224.19,2528.26 4224.19,2461.6
  lines w15: 4164.4,1816.6 9373.01,1816.6 ; 4164.4,2716.6 9373.01,2716.6 ; 4715.28,1666.6 4715.28,2866.6 ; 5255.14,1666.6 5255.14,2866.6 ; 6404.8,1666.6 6404.8,2866.6 ; 6910.68,1666.6 6910.68,2866.6 ; 7644.48,1666.6 7644.48,2866.6 ; 8750.16,1666.6 8750.16,2866.6 ; 4164.4,1666.6 9373.01,1666.6 9373.01,2866.6 4164.4,2866.6 4164.4,1666.6
  text "DRILL TABLE:" at 4165.14,2810.36 h80
  text "Symbol" at 4254.4,2761.6 h72
  text "Count" at 4760.28,2761.6 h72
  text "Hole Size" at 5300.14,2761.6 h72
  text "Plated" at 6449.8,2761.6 h72
  text "Hole Type" at 6955.68,2761.6 h72
  text "Tolerance(Mils)" at 7689.48,2761.6 h72
  text "Tenting" at 8795.16,2761.6 h72
  text "30" at 4760.28,2611.6 h60
  text "12.00mil (0.305mm)" at 5300.14,2611.6 h60
  text "PTH" at 6449.8,2611.6 h60
  text "Round" at 6955.68,2611.6 h60
  text "+0/-12" at 7689.48,2611.6 h60
  text "Both" at 8795.16,2611.6 h60
  text "A" at 4225.31,2601.61 h66.67
  text "7" at 4760.28,2461.6 h60
  text "40.00mil (1.016mm)" at 5300.14,2461.6 h60
  text "PTH" at 6449.8,2461.6 h60
  text "Round" at 6955.68,2461.6 h60
  text "6" at 4760.28,2311.6 h60
  text "214.57mil (5.450mm)" at 5300.14,2311.6 h60
  text "PTH" at 6449.8,2311.6 h60
  text "Round" at 6955.68,2311.6 h60
  text "+/-3" at 7689.48,2311.6 h60
  text "E" at 4225.31,2301.61 h66.67
  text "4" at 4760.28,2161.6 h60
  text "63.00mil (1.600mm)" at 5300.14,2161.6 h60
  text "PTH" at 6449.8,2161.6 h60
  text "Round" at 6955.68,2161.6 h60
  text "+/-3" at 7689.48,2161.6 h60
  text "B" at 4225.31,2151.61 h66.67
  text "4" at 4760.28,2011.6 h60
  text "125.98mil (3.200mm)" at 5300.14,2011.6 h60
  text "PTH" at 6449.8,2011.6 h60
  text "Round" at 6955.68,2011.6 h60
  text "+/-3" at 7689.48,2011.6 h60
  text "D" at 4225.31,2001.61 h66.67
  text "2" at 4760.28,1861.6 h60
  text "64.96mil (1.650mm)" at 5300.14,1861.6 h60
  text "PTH" at 6449.8,1861.6 h60
  text "Round" at 6955.68,1861.6 h60
  text "+/-3" at 7689.48,1861.6 h60
  text "C" at 4225.31,1851.61 h66.67
  text "53 Total" at 4760.28,1711.6 h60
  text ".Layer_Name" at -522.23,-1539.06 h60
M17 Embedded Cavity:
  text ".Layer_Name" at -522.23,-1539.06 h60
M18 Embedded Assembly:
  text ".Layer_Name" at -522.23,-1539.06 h60
M19 Embedded Keepout:
  text ".Layer_Name" at -522.23,-1539.06 h60

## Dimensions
0,0 to -175,-175 on M2 Board Dimensions
0,0 to -175,-175 on M2 Board Dimensions
0,0 to -175,1925 on M2 Board Dimensions
0,0 to 2950,-175 on M2 Board Dimensions
-1099.23,-1080.56 to -99.23,-1080.56 on M2 Board Dimensions
-28.4,-30.18 to -312.94,-250.25 on M2 Board Dimensions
